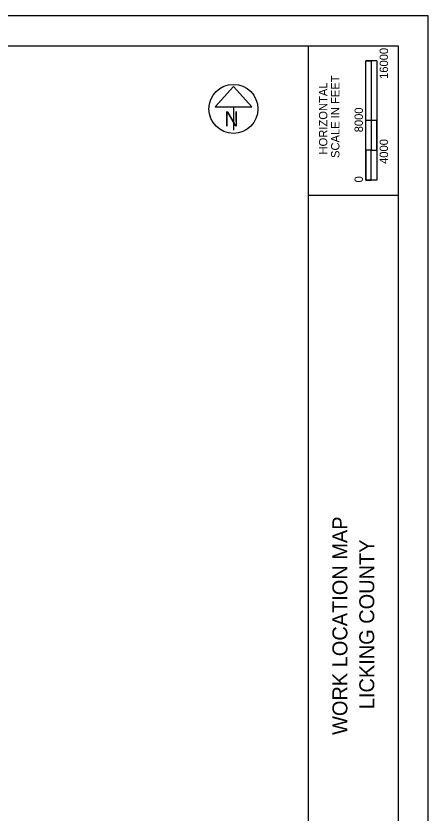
# Model space of a CAD drawing. Extents: x 1853412 to 2125412, y 679418 to 855418.
# Drawn here: x 2070251 to 2125412, y 748607 to 855418 of the extents above; entities that cross this region are included whole.
import ezdxf

# ---------------------------------------------------------------- set-up
doc = ezdxf.new("R2010")
doc.units = 0
for name, color, linetype in [('SH_Border', 7, 'Continuous'), ('SH_Cut_Line', 7, 'Continuous'), ('SH_Data', 7, 'Continuous'), ('SH_Masking', 7, 'Continuous'), ('SH_Text', 7, 'Continuous')]:
    doc.layers.add(name, color=color, linetype=linetype)

msp = doc.modelspace()

# ---------------------------------------------------------------- linework, layer by layer
at = {"layer": 'SH_Border'}
for p, q in [((2109412, 683418), (2109412, 851418)), ((2109412, 831418), (2121412, 831418))]:
    msp.add_line(p, q, dxfattribs=at)
msp.add_lwpolyline([(1865412, 851418), (2121412, 851418), (2121412, 683418), (1865412, 683418)], close=True, dxfattribs=at)
at = {"layer": 'SH_Cut_Line'}
msp.add_lwpolyline([(1853412, 679418), (2125412, 679418), (2125412, 855418), (1853412, 855418)], close=True, dxfattribs=at)
at = {"layer": 'SH_Data'}
for p, q in [((2117065, 833418), (2117065, 849418)), ((2118565, 849418), (2117065, 849418)), ((2117065, 841418), (2117065, 849418)), ((2117065, 849418), (2117812, 849418)), ((2117812, 849418), (2117819, 849418)), ((2117819, 849418), (2117819, 841418)), ((2118565, 849418), (2118565, 833418)), ((2117819, 841418), (2117065, 841418)), ((2118559, 841418), (2117812, 841418)), ((2117812, 841418), (2117812, 837418)), ((2118559, 837418), (2118559, 841418)), ((2117812, 837418), (2117065, 837418)), ((2117065, 837418), (2117065, 833418)), ((2117812, 833418), (2117812, 837418)), ((2117812, 837418), (2118559, 837418)), ((2118565, 833418), (2117065, 833418)), ((2117065, 833418), (2117812, 833418))]:
    msp.add_line(p, q, dxfattribs=at)
at = {"layer": 'SH_Masking'}
msp.add_circle((2099358, 842966), 3280, dxfattribs=at)
at = {"layer": 'SH_Text'}
for p, q in [((2099358, 845956), (2096897, 843226)), ((2101819, 843226), (2099358, 845956)), ((2096897, 843226), (2101819, 843226)), ((2099358, 843226), (2099358, 840132))]:
    msp.add_line(p, q, dxfattribs=at)
msp.add_circle((2099358, 842966), 3280, dxfattribs=at)

# ---------------------------------------------------------------- texts
at = {"layer": 'SH_Data'}
for s, height, p in [('16000', 1120, (2120055, 846977)), ('SCALE IN FEET', 1120, (2113552, 836383)), ('HORIZONTAL', 1120, (2111932, 836852)), ('8000', 1120, (2116696, 839824)), ('4000', 1120, (2120055, 835586)), ('0', 1120, (2116696, 833108)), ('WORK LOCATION MAP', 2000, (2114612, 759077)), ('LICKING COUNTY', 2000, (2118212, 762526))]:
    msp.add_text(s, height=height, rotation=90, dxfattribs=at).set_placement(p)
at = {"layer": 'SH_Text'}
msp.add_text('N', height=2000, dxfattribs=at).set_placement((2098148, 840635))

doc.saveas('drawing.dxf')
